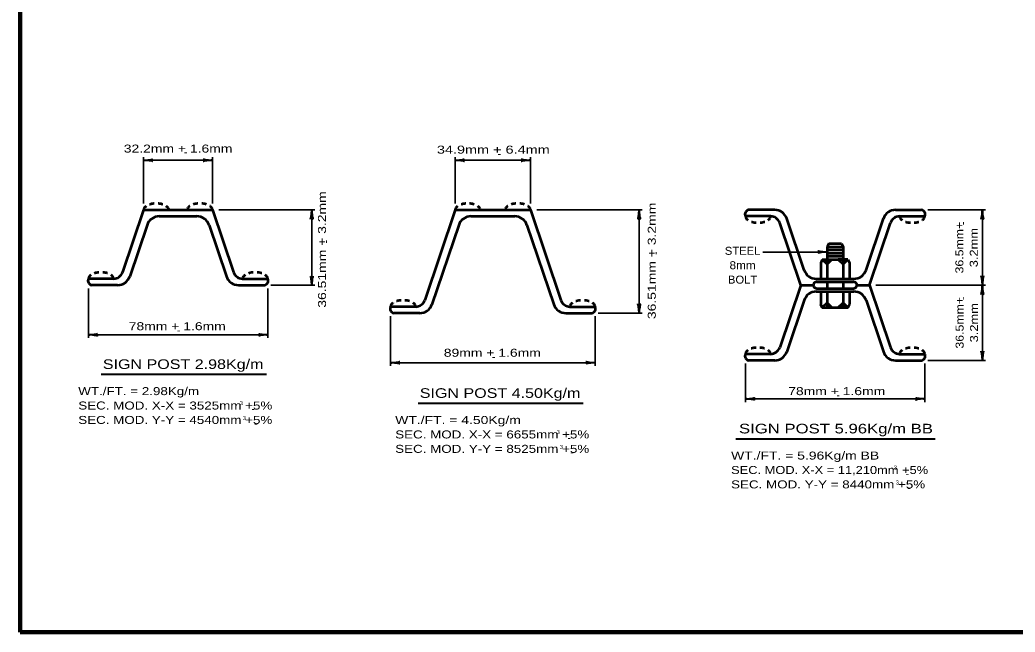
# Model space of a CAD drawing. Extents: x -39 to 816, y -2 to 542.
# Drawn here: x 18 to 390.9, y 9.9 to 239.3 of the extents above; entities that cross this region are included whole.
import ezdxf
from ezdxf.enums import TextEntityAlignment as Align

# ---------------------------------------------------------------- set-up
doc = ezdxf.new("R2010")
doc.units = 0
doc.header["$LTSCALE"] = 1.2
doc.linetypes.add('SHORT_DASHED', pattern=[2.7, 1.5, -1.2])
doc.layers.add('1', color=7, linetype='Continuous', lineweight=53)

msp = doc.modelspace()

# ---------------------------------------------------------------- linework, layer by layer
at = {"layer": '1', "lineweight": 35}
for p, q in [((64.354, 170.523), (64.354, 187.923)), ((64.354, 186.723), (90.154, 186.723)), ((90.154, 170.523), (90.154, 187.923)), ((181.115, 170.523), (181.115, 187.923)), ((181.115, 186.723), (209.315, 186.723)), ((209.315, 170.523), (209.315, 187.923)), ((92.554, 168.123), (128.554, 168.123)), ((127.354, 168.123), (127.354, 139.884)), ((211.715, 168.123), (251.244, 168.123)), ((250.044, 168.123), (250.044, 129.418)), ((358.292, 168.123), (379.892, 168.123)), ((320.492, 152.34), (296.427, 152.34)), ((43.654, 138.723), (43.654, 120.123)), ((110.854, 138.723), (110.854, 120.123)), ((112.054, 139.884), (128.554, 139.884)), ((338.792, 139.923), (379.892, 139.923)), ((156.885, 128.256), (156.885, 109.656)), ((233.544, 128.256), (233.544, 109.656)), ((234.744, 129.418), (251.244, 129.418)), ((43.654, 121.323), (110.854, 121.323)), ((156.885, 110.856), (233.544, 110.856)), ((289.892, 110.523), (289.892, 96.123)), ((357.092, 110.523), (357.092, 96.123)), ((358.292, 111.723), (379.892, 111.723)), ((289.892, 97.323), (357.092, 97.323))]:
    msp.add_line(p, q, dxfattribs=at)
at = {"layer": '1'}
for p, q in [((64.354, 168.123), (56.48, 144.772)), ((64.354, 168.123), (90.154, 168.123)), ((90.154, 168.123), (98.028, 144.772)), ((181.115, 168.123), (169.712, 134.306)), ((181.115, 168.123), (209.315, 168.123)), ((209.315, 168.123), (220.718, 134.306)), ((300.845, 168.123), (291.092, 168.123)), ((346.139, 168.123), (355.892, 168.123)), ((70.201, 165.723), (84.307, 165.723)), ((186.962, 165.723), (203.468, 165.723)), ((299.307, 165.723), (289.892, 165.723)), ((311.89, 145.589), (305.393, 164.856)), ((335.093, 145.589), (341.59, 164.856)), ((347.677, 165.723), (357.092, 165.723)), ((65.653, 162.457), (59.156, 143.189)), ((88.855, 162.457), (95.353, 143.189)), ((182.413, 162.457), (172.387, 132.723)), ((208.016, 162.457), (218.043, 132.723)), ((310.592, 139.923), (302.718, 163.273)), ((336.392, 139.923), (344.266, 163.273)), ((321.092, 155.523), (320.492, 154.323)), ((320.492, 154.323), (326.492, 154.323)), ((320.492, 153.123), (326.492, 153.123)), ((321.092, 155.523), (325.892, 155.523)), ((325.892, 155.523), (326.492, 154.323)), ((318.692, 149.523), (318.092, 148.323)), ((318.692, 149.523), (328.292, 149.523)), ((320.492, 151.923), (326.492, 151.923)), ((320.492, 150.723), (326.224, 150.723)), ((326.454, 150.723), (326.492, 150.723)), ((328.292, 149.523), (328.892, 148.323)), ((318.092, 148.323), (318.092, 142.323)), ((328.892, 148.323), (328.892, 142.323)), ((53.069, 142.323), (43.654, 142.323)), ((101.439, 142.323), (110.854, 142.323)), ((316.439, 142.323), (330.545, 142.323)), ((54.607, 139.923), (44.854, 139.923)), ((99.901, 139.923), (109.654, 139.923)), ((310.592, 139.923), (302.718, 116.572)), ((310.592, 139.923), (315.328, 139.923)), ((316.592, 141.123), (330.392, 141.123)), ((316.592, 138.723), (330.392, 138.723)), ((320.492, 141.123), (320.492, 138.723)), ((326.492, 141.123), (326.492, 138.723)), ((331.655, 139.923), (336.392, 139.923)), ((336.392, 139.923), (344.266, 116.572)), ((316.439, 137.523), (330.545, 137.523)), ((318.092, 137.523), (318.092, 132.723)), ((320.492, 137.523), (320.492, 131.523)), ((326.492, 137.523), (326.492, 131.523)), ((328.892, 137.523), (328.892, 132.723)), ((166.3, 131.856), (156.885, 131.856)), ((224.129, 131.856), (233.544, 131.856)), ((311.89, 134.257), (305.393, 114.989)), ((318.692, 131.523), (318.092, 132.723)), ((318.692, 131.523), (328.292, 131.523)), ((328.292, 131.523), (328.892, 132.723)), ((335.093, 134.257), (341.59, 114.989)), ((167.839, 129.456), (158.085, 129.456)), ((222.591, 129.456), (232.344, 129.456)), ((299.307, 114.123), (289.892, 114.123)), ((347.677, 114.123), (357.092, 114.123)), ((300.845, 111.723), (291.092, 111.723)), ((346.139, 111.723), (355.892, 111.723))]:
    msp.add_line(p, q, dxfattribs=at)
at = {"layer": '1', "lineweight": 40}
for p, q in [((48.452, 106.514), (110.33, 106.514)), ((167.237, 95.68), (229.115, 95.68)), ((286.293, 82.36), (361.044, 82.36))]:
    msp.add_line(p, q, dxfattribs=at)
at = {"layer": '1', "lineweight": 158}
msp.add_line((809.673, 9.927), (18.073, 9.927), dxfattribs=at)
msp.add_lwpolyline([(809.673, 536.027), (17.973, 535.927), (18.073, 9.927)], dxfattribs=at)
at = {"layer": '1', "lineweight": 35}
msp.add_lwpolyline([(378.692, 168.123), (378.692, 139.923), (378.692, 111.723)], dxfattribs=at)
at = {"layer": '1'}
for points in [[(320.492, 154.323), (320.492, 149.523), (320.492, 142.323)], [(326.492, 154.323), (326.492, 149.523), (326.492, 142.323)]]:
    msp.add_lwpolyline(points, dxfattribs=at)
for points in [[(318.692, 149.523), (322.292, 149.523), (320.492, 147.723)], [(328.292, 149.523), (324.692, 149.523), (326.492, 147.723)], [(320.492, 133.323), (318.692, 131.523), (322.292, 131.523)], [(324.692, 131.523), (326.492, 133.323), (328.292, 131.523)]]:
    msp.add_lwpolyline(points, close=True, dxfattribs=at)
for centre, radius, start, end in [((291.41, 166.464), 1.689, 100.85533, 206.01456), ((300.845, 163.323), 4.8, 18.63408, 90), ((346.139, 163.323), 4.8, 90, 161.36561), ((355.573, 166.464), 1.689, 333.98544, 79.14467), ((70.201, 160.923), 4.8, 90, 161.36475), ((84.307, 160.923), 4.8, 18.63465, 90), ((186.962, 160.923), 4.8, 90, 161.36475), ((203.468, 160.923), 4.8, 18.63465, 90), ((299.307, 162.123), 3.6, 18.63464, 90), ((347.677, 162.123), 3.6, 90, 161.36548), ((316.439, 147.123), 4.8, 198.63525, 270), ((330.545, 147.123), 4.8, 270, 341.36535), ((45.172, 141.582), 1.689, 153.98544, 259.14467), ((53.069, 145.923), 3.6, 270, 341.36536), ((54.607, 144.723), 4.8, 270, 341.36592), ((99.901, 144.723), 4.8, 198.63439, 270), ((101.439, 145.923), 3.6, 198.63452, 270), ((109.336, 141.582), 1.689, 280.85533, 26.01456), ((316.53, 139.923), 1.202, 87.05408, 272.94592), ((330.453, 139.923), 1.202, 267.05408, 92.94592), ((166.3, 135.456), 3.6, 270, 341.36536), ((224.129, 135.456), 3.6, 198.63452, 270), ((316.439, 132.723), 4.8, 90, 161.36475), ((330.545, 132.723), 4.8, 18.63465, 90), ((158.404, 131.115), 1.689, 153.98544, 259.14467), ((167.839, 134.256), 4.8, 270, 341.36592), ((222.591, 134.256), 4.8, 198.63439, 270), ((232.026, 131.115), 1.689, 280.85533, 26.01456), ((299.307, 117.723), 3.6, 270, 341.36536), ((347.677, 117.723), 3.6, 198.63452, 270), ((291.41, 113.382), 1.689, 153.98544, 259.14467), ((300.845, 116.523), 4.8, 270, 341.36592), ((346.139, 116.523), 4.8, 198.63439, 270), ((355.573, 113.382), 1.689, 280.85533, 26.01456)]:
    msp.add_arc(centre, radius, start, end, dxfattribs=at)
at = {"layer": '1', "lineweight": 40}
for centre, major_axis, ratio, start_param, end_param in [((65.663, 187.054), (-2.143, -0.187), 0.122415, 0.8963533, 3.1415927), ((65.699, 186.469), (-2.108, 0.211), 0.07063, 3.1407148, 5.41811), ((88.845, 186.391), (2.143, 0.187), 0.122415, 0.8963533, 3.1415927), ((88.809, 186.977), (2.108, -0.211), 0.07063, 3.1407148, 5.41811), ((182.459, 186.469), (-2.108, 0.211), 0.07063, 3.1407148, 5.41811), ((182.459, 186.469), (-2.108, 0.211), 0.07063, 3.1407148, 5.41811), ((182.424, 187.054), (-2.143, -0.187), 0.122415, 0.8963533, 3.1415927), ((182.424, 187.054), (-2.143, -0.187), 0.122415, 0.8963533, 3.1415927), ((208.005, 186.391), (2.143, 0.187), 0.122415, 0.8963533, 3.1415927), ((207.97, 186.977), (2.108, -0.211), 0.07063, 3.1407148, 5.41811), ((127.1, 166.778), (0.211, 2.108), 0.07063, 3.1407148, 5.41811), ((127.1, 166.778), (0.211, 2.108), 0.07063, 3.1407148, 5.41811), ((127.686, 166.813), (-0.187, 2.143), 0.122415, 0.8963533, 3.1415927), ((127.686, 166.813), (-0.187, 2.143), 0.122415, 0.8963533, 3.1415927), ((249.79, 166.778), (0.211, 2.108), 0.07063, 3.1407148, 5.41811), ((249.79, 166.778), (0.211, 2.108), 0.07063, 3.1407148, 5.41811), ((250.376, 166.813), (-0.187, 2.143), 0.122415, 0.8963533, 3.1415927), ((250.376, 166.813), (-0.187, 2.143), 0.122415, 0.8963533, 3.1415927), ((378.438, 166.778), (0.211, 2.108), 0.07063, 3.1407148, 5.41811), ((379.023, 166.813), (-0.187, 2.143), 0.122415, 0.8963533, 3.1415927), ((319.182, 152.009), (2.143, 0.187), 0.122415, 0.8963533, 3.1415927), ((319.147, 152.594), (2.108, -0.211), 0.07063, 3.1407148, 5.41811), ((127.022, 141.194), (0.187, -2.143), 0.122415, 0.8963533, 3.1415927), ((127.608, 141.229), (-0.211, -2.108), 0.07063, 3.1407148, 5.41811), ((378.36, 141.232), (0.187, -2.143), 0.122415, 0.8963533, 3.1415927), ((378.36, 141.232), (0.187, -2.143), 0.122415, 0.8963533, 3.1415927), ((378.946, 141.267), (-0.211, -2.108), 0.07063, 3.1407148, 5.41811), ((378.946, 141.267), (-0.211, -2.108), 0.07063, 3.1407148, 5.41811), ((378.438, 138.578), (0.211, 2.108), 0.07063, 3.1407148, 5.41811), ((378.438, 138.578), (0.211, 2.108), 0.07063, 3.1407148, 5.41811), ((379.023, 138.613), (-0.187, 2.143), 0.122415, 0.8963533, 3.1415927), ((379.023, 138.613), (-0.187, 2.143), 0.122415, 0.8963533, 3.1415927), ((249.712, 130.728), (0.187, -2.143), 0.122415, 0.8963533, 3.1415927), ((250.298, 130.763), (-0.211, -2.108), 0.07063, 3.1407148, 5.41811), ((44.963, 121.654), (-2.143, -0.187), 0.122415, 0.8963533, 3.1415927), ((44.963, 121.654), (-2.143, -0.187), 0.122415, 0.8963533, 3.1415927), ((44.999, 121.069), (-2.108, 0.211), 0.07063, 3.1407148, 5.41811), ((44.999, 121.069), (-2.108, 0.211), 0.07063, 3.1407148, 5.41811), ((109.545, 120.991), (2.143, 0.187), 0.122415, 0.8963533, 3.1415927), ((109.509, 121.577), (2.108, -0.211), 0.07063, 3.1407148, 5.41811), ((378.36, 113.032), (0.187, -2.143), 0.122415, 0.8963533, 3.1415927), ((378.946, 113.067), (-0.211, -2.108), 0.07063, 3.1407148, 5.41811), ((158.23, 110.602), (-2.108, 0.211), 0.07063, 3.1407148, 5.41811), ((158.23, 110.602), (-2.108, 0.211), 0.07063, 3.1407148, 5.41811), ((158.195, 111.188), (-2.143, -0.187), 0.122415, 0.8963533, 3.1415927), ((158.195, 111.188), (-2.143, -0.187), 0.122415, 0.8963533, 3.1415927), ((232.235, 110.525), (2.143, 0.187), 0.122415, 0.8963533, 3.1415927), ((232.199, 111.11), (2.108, -0.211), 0.07063, 3.1407148, 5.41811), ((291.236, 97.069), (-2.108, 0.211), 0.07063, 3.1407148, 5.41811), ((291.236, 97.069), (-2.108, 0.211), 0.07063, 3.1407148, 5.41811), ((291.201, 97.654), (-2.143, -0.187), 0.122415, 0.8963533, 3.1415927), ((291.201, 97.654), (-2.143, -0.187), 0.122415, 0.8963533, 3.1415927), ((355.782, 96.991), (2.143, 0.187), 0.122415, 0.8963533, 3.1415927), ((355.747, 97.577), (2.108, -0.211), 0.07063, 3.1407148, 5.41811)]:
    msp.add_ellipse(centre, major_axis=major_axis, ratio=ratio, start_param=start_param, end_param=end_param, dxfattribs=at)
at = {"layer": '1', "linetype": 'SHORT_DASHED'}
for centre, major_axis, start_param, end_param in [((69.061, 168.123), (4.707, 0), 6.2831853, 9.424778), ((85.447, 168.123), (-4.707, 0), 3.1415927, 6.2831853), ((185.822, 168.123), (4.707, 0), 6.2831853, 9.424778), ((204.607, 168.123), (-4.707, 0), 3.1415927, 6.2831853), ((294.599, 165.723), (4.707, 0), 3.1415927, 6.2831853), ((352.384, 165.723), (-4.707, 0), 6.2831853, 9.424778), ((48.361, 142.323), (4.707, 0), 6.2831853, 9.424778), ((106.147, 142.323), (-4.707, 0), 3.1415927, 6.2831853), ((161.593, 131.856), (4.707, 0), 6.2831853, 9.424778), ((228.837, 131.856), (-4.707, 0), 3.1415927, 6.2831853), ((294.599, 114.123), (4.707, 0), 6.2831853, 9.424778), ((352.384, 114.123), (-4.707, 0), 3.1415927, 6.2831853)]:
    msp.add_ellipse(centre, major_axis=major_axis, ratio=0.50983, start_param=start_param, end_param=end_param, dxfattribs=at)

# ---------------------------------------------------------------- texts
at = {"layer": '1'}
for s, height, width, p in [('32.2mm + 1.6mm', 3, 1.3, (77.259, 189.595)), ('34.9mm + 6.4mm', 3, 1.35, (195.398, 189.202)), ('STEEL', 3, 1.05, (288.828, 151.293)), ('8mm', 3, 1.1, (288.828, 145.893)), ('BOLT', 3, 1.05, (288.828, 140.493)), ('78mm + 1.6mm', 3, 1.3, (76.947, 123.04)), ('89mm + 1.6mm', 3, 1.3, (195.022, 113.095)), ('SIGN POST 2.98Kg/m', 3.6, 1.25, (79.15, 108.525)), ('SIGN POST 4.50Kg/m', 3.6, 1.25, (197.935, 97.691)), ('78mm + 1.6mm', 3, 1.3, (324.105, 98.709)), ('SIGN POST 5.96Kg/m BB', 3.6, 1.3, (323.822, 84.371))]:
    msp.add_text(s, height=height, dxfattribs=dict(at, width=width)).set_placement(p, align=Align.CENTER)
for p in [(80.046, 188.305), (197.651, 187.734), (77.486, 121.581), (195.561, 111.635), (324.644, 97.25), (105.403, 92.128), (106.509, 86.72), (223.833, 81.294), (224.85, 75.886), (350.519, 67.886), (351.181, 62.566)]:
    msp.add_text('-', height=3, dxfattribs=at).set_placement(p, align=Align.CENTER)
for s, width, p in [('36.51mm + 3.2mm', 1.3, (132.703, 153.275)), ('36.51mm + 3.2mm', 1.3, (256.281, 149.013)), ('36.5mm+', 1.15, (371.567, 153.985)), ('3.2mm', 1.2, (376.967, 153.985)), ('36.5mm+', 1.15, (371.656, 125.836)), ('3.2mm', 1.2, (377.056, 125.836))]:
    msp.add_text(s, height=3, rotation=90, dxfattribs=dict(at, width=width)).set_placement(p, align=Align.CENTER)
for p in [(372.761, 163.094), (134.037, 156.167), (257.616, 151.905), (372.85, 134.944)]:
    msp.add_text('-', height=3, rotation=90, dxfattribs=at).set_placement(p, align=Align.CENTER)
for s, height, width, p in [('WT./FT. = 2.98Kg/m', 3, 1.25, (39.841, 98.718)), ('SEC. MOD. X-X = 3525mm +5%', 3, 1.25, (39.841, 93.318)), ('3', 1.5, 0.9, (100.387, 94.979)), ('SEC. MOD. Y-Y = 4540mm +5%', 3, 1.25, (39.841, 87.918)), ('3', 1.5, 0.9, (101.541, 89.385)), ('WT./FT. = 4.50Kg/m', 3, 1.3, (158.626, 87.885)), ('SEC. MOD. X-X = 6655mm +5%', 3, 1.25, (158.626, 82.485)), ('3', 1.5, 0.9, (219.172, 84.145)), ('SEC. MOD. Y-Y = 8525mm +5%', 3, 1.25, (158.626, 77.085)), ('3', 1.5, 0.9, (220.326, 78.551)), ('WT./FT. = 5.96Kg/m BB', 3, 1.3, (284.513, 74.565)), ('SEC. MOD. X-X = 11,210mm +5%', 3, 1.2, (284.513, 69.165)), ('3', 1.5, 0.9, (345.503, 70.826)), ('SEC. MOD. Y-Y = 8440mm +5%', 3, 1.25, (284.513, 63.765)), ('3', 1.5, 0.9, (346.213, 65.231))]:
    msp.add_text(s, height=height, dxfattribs=dict(at, width=width)).set_placement(p)

doc.saveas('drawing.dxf')
